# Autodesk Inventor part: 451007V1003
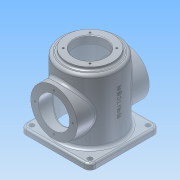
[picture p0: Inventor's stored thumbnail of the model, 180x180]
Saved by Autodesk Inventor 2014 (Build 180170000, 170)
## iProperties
Created: 2015-10
Part Number: 451007V1003
Material: 알루미늄 6061
Document SubType Name: Modeling
Designer: net
Density: 2.71 g/cm^3
Appearance: 알루미늄 - 평지
Mass: 986.454 g
Surface Area: 1039.31 cm^2
Volume: 364.005 cm^3
Author: net
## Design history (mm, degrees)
sketch "스케치1"
  geometry: C1 r 50 at (0, 0); 1 further point
  constraints: 1 centre point, 1 coincident
  dimensions: "d0" = 50 radius of C1
extrude "돌출1" new body sketch "스케치1" distance "d1" = 110; taper "d2" = 0 deg
sketch "스케치2"
  geometry: C1 r 50 at (0, 0) reference; C2 r 40 at (0, 0)
  constraints: 1 centre point, 1 coincident
  dimensions: "d3" = 40 radius of C2
extrude "돌출2" join sketch "스케치2" distance "d4" = 5; taper "d5" = 0 deg
sketch "스케치3"
  geometry: L1 (-60, 60)-(60, 60); L2 (60, 60)-(60, -60); L3 (60, -60)-(-60, -60); L4 (-60, -60)-(-60, 60); L5 (-60, 60)-(60, -60); L6 (60, 60)-(-60, -60); C1 r 50 at (0, 0) reference
  constraints: 12 end point, 2 midpoint, 2 parallel, 1 horizontal, 1 perpendicular
  dimensions: "d6" = 120 distance of L2.end L3.end; "d7" = 120 distance of L1.end L2.end
extrude "돌출3" join sketch "스케치3" distance "d8" = 10; taper "d9" = 0 deg
sketch "스케치4"
  geometry: L1 (60, 60)-(-60, 60) reference; L2 (-60, 60)-(-60, -60) reference; C1 r 4 at (-50, 50)
  constraints: 1 centre point
  dimensions: "d14" = 8 diameter of C1; "d15" = 10 distance from line of L1 C1.centre; "d16" = 10 distance from line of L2 C1.centre
extrude "돌출4" cut sketch "스케치4" stored distance "d17" = 10; taper "d18" = 0 deg
fillet "모깎기1" dims "d25" = 10
fillet "모깎기2" dims "d26" = 3
sketch "스케치5"
  geometry: C1 r 45 at (0, 0); 1 further point
  constraints: 1 centre point, 1 coincident
  dimensions: "d27" = 45 radius of C1
extrude "돌출5" cut sketch "스케치5" distance "d28" = 112; taper "d29" = 0 deg
sketch "스케치6"
  geometry: C1 r 45 at (0, 0) reference; C2 r 27 at (0, 0)
  constraints: 1 centre point, 1 coincident
  dimensions: "d30" = 27 radius of C2
extrude "돌출6" cut sketch "스케치6" distance "d31" = 13; taper "d32" = 0 deg
sketch "스케치7"
  geometry: L1 (0, 0)-(22.981, 22.981); L2 (0, 0)-(32.5, 0); C1 r 40 at (0, 0) reference; C2 r 32.5 at (0, 0); 1 further point
  constraints: 4 end point, 2 coincident, 1 centre point, 1 equal length, 1 horizontal
  dimensions: "d33" = 32.5 radius of C2; "d34" = 32.5 distance of L1.start L1.end; "d35" = 45 deg angle of L2 L1
hole "구멍1" sketch "스케치7" at (22.981, 22.981) diameter "d36" = 3.242; stored, may be unused: countersink angle "d40" = 90 deg, drill point angle "d42" = 118 deg; dims "d37" = 8, "d38" = 4, "d39" = 2, "d41" = 10
fillet "모깎기3" dims "d46" = 5
node "작업 평면2"
sketch "스케치9" dims "d1" = 110, "d2" = 0
  geometry: L1 (50, -10)-(-50, -10) reference; L2 (40, 115)-(-40, 115) reference; 3 further points
  constraints: 1 midpoint, 1 vertical alignment, 1 other
  dimensions: "d49" = 70 distance from line of L1 point (0, 60)
feature "엠보싱1" sketch "스케치9" dims "d50" = 0.5, "d51" = 0
node "작업 평면3"
sketch "스케치10"
  geometry: L1 (50, -10)-(-50, -10) reference; L2 (40, 115)-(-40, 115) reference; C1 r 40 at (0, 50); 2 further points
  constraints: 1 centre point, 1 midpoint, 1 vertical alignment
  dimensions: "d53" = 40 radius of C1; "d54" = 60 distance from line of L1 C1.centre
extrude "돌출7" join sketch "스케치10" stored distance "d55" = 13; taper "d56" = 0 deg
sketch "스케치11"
  geometry: C1 r 40 at (0, 0) reference; C2 r 27 at (0, 0); 1 further point
  constraints: 1 centre point, 1 coincident
  dimensions: "d57" = 27 radius of C2
extrude "돌출8" cut sketch "스케치11" stored distance "d58" = 13; taper "d59" = 0 deg
sketch "스케치12" dims "d60" = 32.5
  geometry: C1 r 27 at (0, 0) reference; C2 r 40 at (0, 0) reference; 3 further points
  constraints: 2 horizontal alignment, 1 coincident, 2 other
hole "구멍2" sketch "스케치12" at (-32.5, 0) diameter "d61" = 3.242; stored, may be unused: countersink angle "d65" = 90 deg, drill point angle "d67" = 118 deg; dims "d62" = 8, "d63" = 4, "d64" = 2, "d66" = 10
fillet "모깎기4" dims "d71" = 5
fillet "모깎기5" dims "d72" = 3, "d80" = 5
fillet "모깎기6" dims "d73" = 3
chamfer "모따기1" distance "d74" = 3; stored, may be unused: second distance "d75" = 2, angle "d76" = 45 deg
chamfer "모따기2" distance "d77" = 1; stored, may be unused: second distance "d78" = 2, angle "d79" = 45 deg
node "솔리드1"
pattern_linear "직사각형 패턴1" dims "d21" = 100
pattern_circular "원형 패턴1" dims angle "d44" = 360 deg
mirror "대칭1"
pattern_circular "원형 패턴2" dims angle "d69" = 360 deg
mirror "대칭2"
other parameters: "d52" = 62
